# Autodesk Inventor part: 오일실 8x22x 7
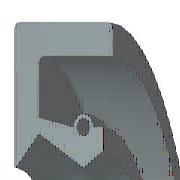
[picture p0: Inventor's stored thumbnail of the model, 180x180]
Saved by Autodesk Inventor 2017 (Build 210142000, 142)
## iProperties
IsCustomPart: 1
Created: 2012-02
Part Number: 오일실 8x22x 7
Material: 고무
Description: 오일-실
Document SubType Name: Modeling
Standard: KS B 2804
Designer: mduedu
Standards Organization: KS
Language: ko-KR
Size Designation: D - 8 22 7
Categories: <MemberInstance><Categories><Category DisplayName="샤프트 부품" InternalName="7f7aeb1f-a693-4053-b835-cee3144e0d98" Mnemonic="SHFT"><Category DisplayName="실링" Intern
Density: 0.93 g/cm^3
Appearance: 고무 - 검은색 - 버전 1.1
Mass: 1.28441 g
Surface Area: 18.2787 cm^2
Volume: 1.38108 cm^3
Author: mduedu
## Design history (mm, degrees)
revolve "본체" stored, may be unused: angle "d17" = 90 deg
revolve "스프링1" stored, may be unused: angle "d18" = 90 deg
body "Solid1"
sketch "스케치1"
  geometry: L1 (0, 11)-(7, 11); L2 (7, 9.25)-(1.75, 9.25); L3 (1.75, 5.75)-(4.9, 4); L4 (4.9, 4)-(0, 4); L5 (0, 0)-(9.586, 0) reference; L6 (4.9, 4)-(6.3, 4.875); L7 (0, 18)-(0, -3) reference; L8 (-1.941, 0)-(11.507, 0) reference; L9 (4.2, 6.1)-(1.75, 6.59); L10 (1.75, 6.59)-(1.75, 9.25); L11 (0, 11)-(0, 4.088); L12 (4.9, 4)-(0, 4); L13 (1.75, 5.75)-(0.152, 4.028); L14 (7, 11)-(7, 9.25); L15 (5.6, 6.1)-(6.3, 6.1); L16 (6.3, 6.1)-(6.3, 4.875); C1 r 0.455 at (4.9, 6.1); A1 r 0.7 centre (4.9, 6.1) between (5.6, 6.1) and (4.2, 6.1); A2 r 0.088 centre (0.088, 4.088) between (0, 4.088) and (0.152, 4.028); 1 further point
  constraints: 28 end point, 5 horizontal alignment, 5 point on line, 4 point on circle, 4 vertical alignment, 3 centre point, 3 tangent, 2 collinear, 2 horizontal, 2 perpendicular, 1 coincident, 1 parallel
  dimensions: "d0" = 22 diameter of L1 L5 (= SD2); "d1" = 1.75 distance of L1.end L2.start (= SD); "d2" = 0.91 diameter of C1 (= SPDI); "d3" = 1.4 diameter of A1 (= SPDA); "d4" = 8 diameter of L3.end L5 (= NND); "d5" = 11.5 diameter of L3.start L5 (= TKDM); "d7" = 13.18 diameter of L9.end L5 (= TKDM + 0.24 x SWDT); "d8" = 1.75 distance between parallel lines of L11 L10 (= SD); "d9" = 4.9 distance from line of L11 C1.centre (= SPDST); "d10" = 12.2 diameter of C1.centre L5 (= HLDM); "d11" = 0.0875 radius of A2 (= 0.25 x LAB); "d12" = 6.3 distance between parallel lines of L11 L16 (= SDI); "d13" = 9.75 diameter of L6.end L5 (= ABDM); "d14" = 7 distance from line of L11 L1.end (= SWDT)
fillet "모깎기1" dims "d6" = 0.3 (= RR)
other parameters: "SD2" = 22 [user parameter; used in 1 equation term], "SWDT" = 7 [user parameter; used in 2 equation terms], "RR" = 0.3 [user parameter; used in 1 equation term], "SD" = 1.75 [user parameter; used in 2 equation terms], "NND" = 8 [user parameter; used in 1 equation term], "SPDA" = 1.4 [user parameter; used in 1 equation term], "SPDI" = 0.91 [user parameter; used in 1 equation term], "TKDM" = 11.5 [user parameter; used in 2 equation terms], "HLDM" = 12.2 [user parameter; used in 1 equation term], "ABDM" = 9.75 [user parameter; used in 1 equation term], "SDI" = 6.3 [user parameter; used in 1 equation term], "SPDST" = 4.9 [user parameter; used in 1 equation term], "LAB" = 0.35 [user parameter; used in 1 equation term], "d15" = 0, "d16" = 0, "d19" = 0
